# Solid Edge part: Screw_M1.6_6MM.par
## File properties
Author: hhakima
Template: Normal.par
Last saved by: hhakima
Revision: 6
Application: Solid Edge
Density: 7833.000 kg/m^3
Accuracy: 0.990
Material: Steel
Face Style: Steel
Fill Style: ANSI32(Steel)
Virtual Style: Machined steel
Coef. of Thermal Exp: 1.3e-05
Thermal Conductivity: 32.0
Specific Heat: 481.0
Modulus of Elasticity: 199947953000.0
Poission's Ratio: 0.29
Yield Stress: 262000766.0
Ultimate Stress: 358527364.0
Elongation: 0.0
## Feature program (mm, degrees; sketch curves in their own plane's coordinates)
body "unnamed Body 1"
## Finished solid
Body 1: solid body, 33 faces, 80 edges, 50 vertices.
  Faces by surface: plane 19, cone 5, cylinder 3, spline 3, torus 2, sphere 1
  Edges by curve: circle 33, line 29, intersection 13, spline 5
Bounding box of the edges (mm; curved faces can reach further): 3.200 x 3.200 x 7.341, from (-1.6, -1.6, 0) to (1.6, 1.6, 7.3411).
Cylindrical faces by radius (mm): R0.5727 x1, R0.8 x1, R1.6 x1
Conical faces (half-angle, radius in mm at the cone's reference point): 15 deg R1.25 x4, 45 deg R3.7477 x1
Toroidal faces (ring radius, tube radius in mm): R1.348 r0.252 x2
Spherical faces by radius (mm): R2.1786 x1
Planar faces by outward normal: +z 1, -z 2, oblique 16
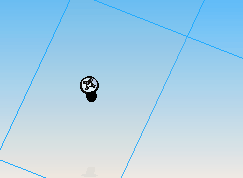
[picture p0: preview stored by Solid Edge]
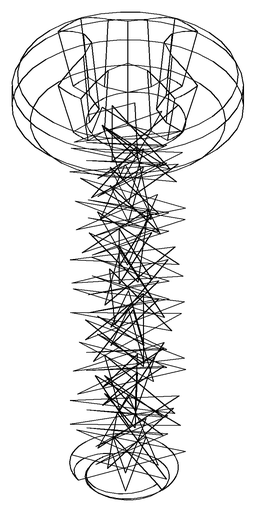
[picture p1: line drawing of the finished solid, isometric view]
